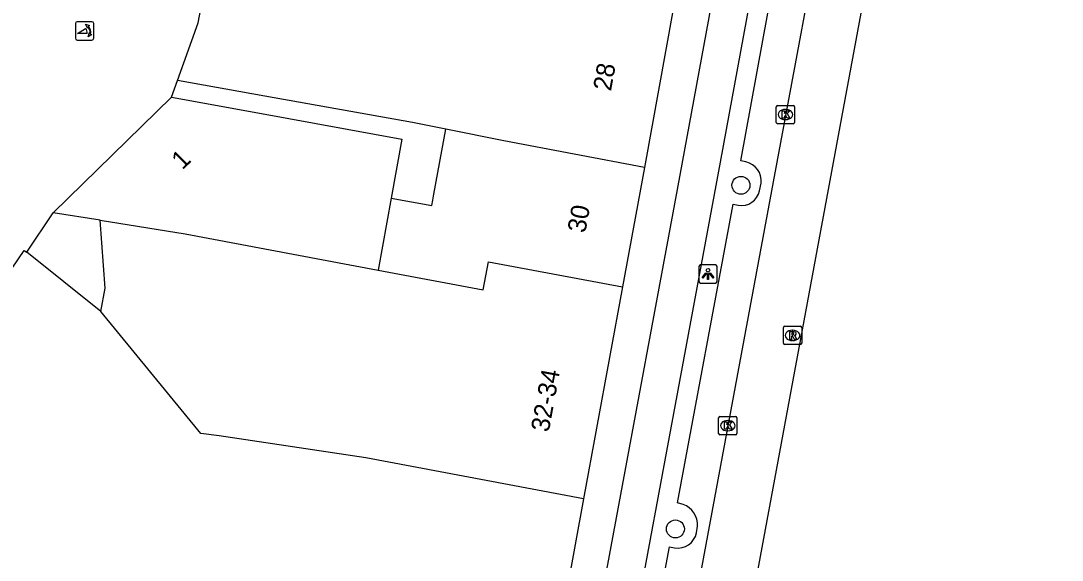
# Model space of a CAD drawing. Extents: x 161402 to 161933, y 381650 to 382313.
# Drawn here: x 161869.9 to 161926.7, y 382017.2 to 382046.6 of the extents above; entities that cross this region are included whole.
import ezdxf

# ---------------------------------------------------------------- set-up
doc = ezdxf.new("R2010")
doc.units = 0
for name, color, linetype in [('IMGEO_Boom', 7, 'Continuous'), ('IMGEO_Fietspad_gesloten', 7, 'Continuous'), ('IMGEO_Kolk', 7, 'Continuous'), ('IMGEO_Lichtpunt', 7, 'Continuous'), ('IMGEO_OVBaan_gesloten', 7, 'Continuous'), ('IMGEO_Pand', 7, 'Continuous'), ('IMGEO_Pand_nummerreeks', 7, 'Continuous'), ('IMGEO_Parkeervlak_open', 7, 'Continuous'), ('IMGEO_Poller', 7, 'Continuous'), ('IMGEO_Rijbaan_lokaal_gesloten', 7, 'Continuous'), ('IMGEO_Rijbaan_lokaal_open', 7, 'Continuous'), ('IMGEO_Rioolput', 7, 'Continuous')]:
    doc.layers.add(name, color=color, linetype=linetype)

msp = doc.modelspace()

# ---------------------------------------------------------------- linework, layer by layer
at = {"layer": 'IMGEO_Boom'}
for centre in [(161909.17, 382037.612), (161905.593, 382018.864)]:
    msp.add_circle(centre, 0.489, dxfattribs=at)
at = {"layer": 'IMGEO_Fietspad_gesloten'}
for points in [[(161887.89, 381941.593), (161898.752, 382000), (161905.702, 382037.375), (161910.061, 382061.001)], [(161869.899, 381834.602), (161881.54, 381896.271), (161882.623, 381902.093), (161888.398, 381933.147), (161890.059, 381942.083), (161900.83, 382000), (161908.061, 382038.88), (161912.039, 382060.567)]]:
    msp.add_lwpolyline(points, dxfattribs=at)
at = {"layer": 'IMGEO_Kolk'}
for p, q in [((161911.173, 382041.973), (161912.025, 382041.973)), ((161911.098, 382041.047), (161911.098, 382041.899)), ((161911.586, 382041.753), (161911.611, 382041.753)), ((161912.099, 382041.899), (161912.099, 382041.047)), ((161912.025, 382040.973), (161911.173, 382040.973)), ((161911.609, 382041.193), (161911.584, 382041.193)), ((161907.951, 382024.074), (161907.951, 382024.926)), ((161908.026, 382025), (161908.878, 382025)), ((161908.952, 382024.926), (161908.952, 382024.074)), ((161908.439, 382024.78), (161908.464, 382024.78)), ((161908.878, 382024), (161908.026, 382024)), ((161908.462, 382024.22), (161908.437, 382024.22))]:
    msp.add_line(p, q, dxfattribs=at)
for points in [[(161911.173, 382041.973), (161912.025, 382041.973)], [(161911.098, 382041.047), (161911.098, 382041.899)], [(161911.419, 382041.673), (161911.542, 382041.673), (161911.542, 382041.522), (161911.672, 382041.673), (161911.836, 382041.673), (161911.69, 382041.522), (161911.843, 382041.273), (161911.691, 382041.273), (161911.606, 382041.437), (161911.542, 382041.37), (161911.542, 382041.273), (161911.419, 382041.273), (161911.419, 382041.673)], [(161912.099, 382041.899), (161912.099, 382041.047)], [(161912.025, 382040.973), (161911.173, 382040.973)], [(161907.951, 382024.074), (161907.951, 382024.926)], [(161908.026, 382025), (161908.878, 382025)], [(161908.952, 382024.926), (161908.952, 382024.074)], [(161908.272, 382024.7), (161908.395, 382024.7), (161908.395, 382024.549), (161908.525, 382024.7), (161908.689, 382024.7), (161908.543, 382024.549), (161908.696, 382024.3), (161908.544, 382024.3), (161908.459, 382024.464), (161908.395, 382024.397), (161908.395, 382024.3), (161908.272, 382024.3), (161908.272, 382024.7)], [(161908.878, 382024), (161908.026, 382024)]]:
    msp.add_lwpolyline(points, dxfattribs=at)
for centre, start, end in [((161911.175, 382041.897), 91.552, 178.448), ((161911.175, 382041.897), 91.552, 178.448), ((161912.023, 382041.897), 1.552, 88.448), ((161912.023, 382041.897), 1.552, 88.448), ((161911.175, 382041.049), 181.552, 268.448), ((161911.175, 382041.049), 181.552, 268.448), ((161912.023, 382041.049), 271.552, 358.448), ((161912.023, 382041.049), 271.552, 358.448), ((161908.028, 382024.924), 91.552, 178.448), ((161908.028, 382024.924), 91.552, 178.448), ((161908.876, 382024.924), 1.552, 88.448), ((161908.876, 382024.924), 1.552, 88.448), ((161908.028, 382024.076), 181.552, 268.448), ((161908.028, 382024.076), 181.552, 268.448), ((161908.876, 382024.076), 271.552, 358.448), ((161908.876, 382024.076), 271.552, 358.448)]:
    msp.add_arc(centre, 0.0765, start, end, dxfattribs=at)
for centre, major_axis, ratio, start_param, end_param in [((161911.585, 382041.473), (-0.387, 0.002), 0.722429, 4.712389, 7.853982), ((161911.61, 382041.473), (-0.39, 0.002), 0.717154, 1.570796, 4.712389), ((161908.438, 382024.5), (-0.387, 0.002), 0.722429, 4.712389, 7.853982), ((161908.463, 382024.5), (-0.39, 0.002), 0.717154, 1.570796, 4.712389)]:
    msp.add_ellipse(centre, major_axis=major_axis, ratio=ratio, start_param=start_param, end_param=end_param, dxfattribs=at)
at = {"layer": 'IMGEO_Lichtpunt'}
for p, q in [((161906.874, 382033.179), (161906.874, 382032.372)), ((161906.874, 382033.179), (161906.874, 382032.372)), ((161907.776, 382033.274), (161906.968, 382033.274)), ((161907.776, 382033.274), (161906.968, 382033.274)), ((161907.87, 382032.372), (161907.87, 382033.179)), ((161907.87, 382032.372), (161907.87, 382033.179)), ((161906.968, 382032.278), (161907.776, 382032.278)), ((161906.968, 382032.278), (161907.776, 382032.278))]:
    msp.add_line(p, q, dxfattribs=at)
for points in [[(161907.248, 382032.843), (161907.287, 382032.815), (161907.099, 382032.553), (161907.061, 382032.58), (161907.248, 382032.843)], [(161907.46, 382032.815), (161907.498, 382032.842), (161907.685, 382032.58), (161907.646, 382032.552), (161907.46, 382032.815)], [(161907.35, 382032.795), (161907.397, 382032.795), (161907.397, 382032.473), (161907.35, 382032.473), (161907.35, 382032.795)]]:
    msp.add_lwpolyline(points, dxfattribs=at)
msp.add_circle((161907.373, 382032.977), 0.0994, dxfattribs=at)
for centre, start, end in [((161906.968, 382033.179), 90, 180), ((161906.968, 382033.179), 90, 180), ((161907.776, 382033.179), 0, 90), ((161907.776, 382033.179), 0, 90), ((161906.968, 382032.372), 180, 270), ((161906.968, 382032.372), 180, 270), ((161907.776, 382032.372), 270, 0), ((161907.776, 382032.372), 270, 360)]:
    msp.add_arc(centre, 0.0946, start, end, dxfattribs=at)
at = {"layer": 'IMGEO_OVBaan_gesloten'}
msp.add_lwpolyline([(161894.174, 381930.698), (161920.066, 382070.485), (161920.568, 382072.989), (161920.797, 382074.121), (161926.695, 382099.95)], dxfattribs=at)
at = {"layer": 'IMGEO_Pand'}
for points in [[(161878.423, 382043.323), (161879.548, 382046.468), (161880.537, 382051.6)], [(161905.504, 382047.572), (161905.48, 382047.22), (161903.899, 382038.59)], [(161893.077, 382040.671), (161891.251, 382041.042), (161883.185, 382042.477), (161878.423, 382043.323)], [(161871.647, 382036.119), (161878.093, 382042.427)], [(161878.093, 382042.427), (161883.013, 382041.531), (161890.672, 382040.135), (161890.09, 382036.919)], [(161890.09, 382036.919), (161892.299, 382036.504), (161892.353, 382036.794), (161892.415, 382037.126), (161893.077, 382040.671)], [(161903.899, 382038.59), (161896.236, 382040.03), (161893.077, 382040.671)], [(161903.899, 382038.59), (161902.704, 382032.073)], [(161890.09, 382036.919), (161889.378, 382032.986)], [(161874.211, 382035.706), (161871.647, 382036.119)], [(161874.247, 382030.726), (161874.485, 382031.994), (161874.211, 382035.706)], [(161874.211, 382035.706), (161878.84, 382034.96), (161889.378, 382032.986)], [(161863.131, 382023.567), (161863.165, 382023.932), (161870.07, 382034.054), (161870.203, 382033.963)], [(161874.247, 382030.726), (161870.203, 382033.963)], [(161889.378, 382032.986), (161895.112, 382031.912), (161895.4, 382033.445), (161902.704, 382032.073)], [(161902.704, 382032.073), (161900.585, 382020.509)], [(161900.585, 382020.509), (161888.702, 382022.741), (161880.709, 382023.945), (161879.703, 382024.079), (161874.247, 382030.726)], [(161900.585, 382020.509), (161898.721, 382010.338)]]:
    msp.add_lwpolyline(points, dxfattribs=at)
at = {"layer": 'IMGEO_Parkeervlak_open'}
for points in [[(161909.441, 382038.888), (161909.164, 382038.94), (161912.699, 382058.251), (161913.017, 382058.21)], [(161910.178, 382037.315), (161910.277, 382037.728)], [(161906.013, 382020.197), (161905.714, 382020.292), (161908.748, 382036.59), (161909.017, 382036.526)], [(161906.752, 382018.65), (161906.794, 382019.011)], [(161903.065, 382004.44), (161902.77, 382004.559), (161905.275, 382017.882), (161905.552, 382017.835)]]:
    msp.add_lwpolyline(points, dxfattribs=at)
for centre, radius, start, end in [((161909.201, 382037.834), 1.081, 354.3944, 77.1655), ((161909.196, 382037.511), 1.001, 259.6899, 348.7091), ((161905.641, 382019.102), 1.157, 355.5035, 71.2275), ((161905.716, 382018.885), 1.062, 261.1287, 347.2374)]:
    msp.add_arc(centre, radius, start, end, dxfattribs=at)
at = {"layer": 'IMGEO_Poller'}
for p, q in [((161873.762, 382046.535), (161872.954, 382046.535)), ((161873.762, 382046.535), (161872.954, 382046.535)), ((161872.86, 382046.44), (161872.86, 382045.633)), ((161872.86, 382046.44), (161872.86, 382045.633)), ((161873.856, 382045.633), (161873.856, 382046.44)), ((161873.856, 382045.633), (161873.856, 382046.44)), ((161872.954, 382045.538), (161873.762, 382045.538)), ((161872.954, 382045.538), (161873.762, 382045.538))]:
    msp.add_line(p, q, dxfattribs=at)
for points in [[(161873.495, 382045.891), (161872.982, 382045.891), (161873.412, 382046.166)], [(161873.539, 382046.264), (161873.527, 382046.191), (161873.402, 382046.396)], [(161873.402, 382046.396), (161873.633, 382046.33), (161873.562, 382046.298)], [(161873.555, 382045.719), (161873.621, 382045.95), (161873.651, 382045.882)], [(161873.687, 382045.855), (161873.759, 382045.844), (161873.555, 382045.719)]]:
    msp.add_lwpolyline(points, dxfattribs=at)
for centre, radius, start, end in [((161872.954, 382046.44), 0.0946, 90, 180), ((161872.954, 382046.44), 0.0946, 90, 180), ((161873.762, 382046.44), 0.0946, 0, 90), ((161873.762, 382046.44), 0.0946, 0, 90), ((161873.167, 382045.941), 0.332, 351.3247, 42.4854), ((161873.181, 382045.951), 0.476, 351.7527, 41.1691), ((161873.181, 382045.951), 0.516, 349.3569, 42.2912), ((161872.954, 382045.633), 0.0946, 180, 270), ((161872.954, 382045.633), 0.0946, 180, 270), ((161873.762, 382045.633), 0.0946, 270, 0), ((161873.762, 382045.633), 0.0946, 270, 0)]:
    msp.add_arc(centre, radius, start, end, dxfattribs=at)
at = {"layer": 'IMGEO_Rijbaan_lokaal_gesloten'}
msp.add_lwpolyline([(161917.217, 382071.563), (161910.924, 382037.806), (161903.912, 382000), (161894.985, 381951.871)], dxfattribs=at)
at = {"layer": 'IMGEO_Rijbaan_lokaal_open'}
for points in [[(161878.093, 382042.427), (161878.423, 382043.323)], [(161870.203, 382033.963), (161871.647, 382036.119)]]:
    msp.add_lwpolyline(points, dxfattribs=at)
at = {"layer": 'IMGEO_Rioolput'}
for p, q in [((161911.485, 382028.996), (161911.485, 382029.848)), ((161911.56, 382029.922), (161912.412, 382029.922)), ((161911.973, 382029.702), (161911.998, 382029.702)), ((161912.486, 382029.848), (161912.486, 382028.996)), ((161912.412, 382028.922), (161911.56, 382028.922)), ((161911.996, 382029.142), (161911.971, 382029.142))]:
    msp.add_line(p, q, dxfattribs=at)
for points in [[(161911.485, 382028.996), (161911.485, 382029.848)], [(161911.56, 382029.922), (161912.412, 382029.922)], [(161912.074, 382029.62), (161911.822, 382029.622), (161911.822, 382029.222)], [(161912, 382029.541), (161911.946, 382029.541), (161911.946, 382029.46)], [(161911.946, 382029.46), (161911.998, 382029.46)], [(161912.486, 382029.848), (161912.486, 382028.996)], [(161912.412, 382028.922), (161911.56, 382028.922)], [(161911.822, 382029.222), (161911.946, 382029.222), (161911.946, 382029.384), (161911.957, 382029.384)], [(161912.004, 382029.355), (161912.075, 382029.222), (161912.215, 382029.222), (161912.15, 382029.348)]]:
    msp.add_lwpolyline(points, dxfattribs=at)
for centre, radius, start, end in [((161911.562, 382029.846), 0.0765, 91.552, 178.448), ((161911.562, 382029.846), 0.0765, 91.552, 178.448), ((161911.982, 382029.649), 0.19, 274.7715, 282.9687), ((161912.006, 382029.445), 0.0964, 77.0061, 93.1865), ((161912.02, 382029.502), 0.0378, 276.6634, 79.6772), ((161912.073, 382029.51), 0.109, 350.3612, 89.416), ((161912.071, 382029.51), 0.112, 277.5842, 350.9817), ((161912.41, 382029.846), 0.0765, 1.552, 88.448), ((161912.41, 382029.846), 0.0765, 1.552, 88.448), ((161911.562, 382028.998), 0.0765, 181.552, 268.448), ((161911.562, 382028.998), 0.0765, 181.552, 268.448), ((161911.956, 382029.331), 0.0533, 26.0293, 88.6989), ((161912.055, 382029.295), 0.108, 29.5134, 73.7905), ((161912.41, 382028.998), 0.0765, 271.552, 358.448), ((161912.41, 382028.998), 0.0765, 271.552, 358.448)]:
    msp.add_arc(centre, radius, start, end, dxfattribs=at)
for centre, major_axis, ratio, start_param, end_param in [((161911.972, 382029.422), (-0.387, 0.002), 0.722429, 4.712389, 7.853982), ((161911.997, 382029.422), (-0.39, 0.002), 0.717154, 1.570796, 4.712389)]:
    msp.add_ellipse(centre, major_axis=major_axis, ratio=ratio, start_param=start_param, end_param=end_param, dxfattribs=at)

# ---------------------------------------------------------------- texts
at = {"layer": 'IMGEO_Pand_nummerreeks'}
for s, rotation, p in [('28', 79.8646, (161902.077, 382042.715)), ('1', 44.2896, (161878.695, 382038.421)), ('30', 79.6182, (161900.675, 382034.975)), ('32-34', 79.6182, (161898.683, 382024.113))]:
    msp.add_text(s, height=1, rotation=rotation, dxfattribs=at).set_placement(p)

doc.saveas('drawing.dxf')
